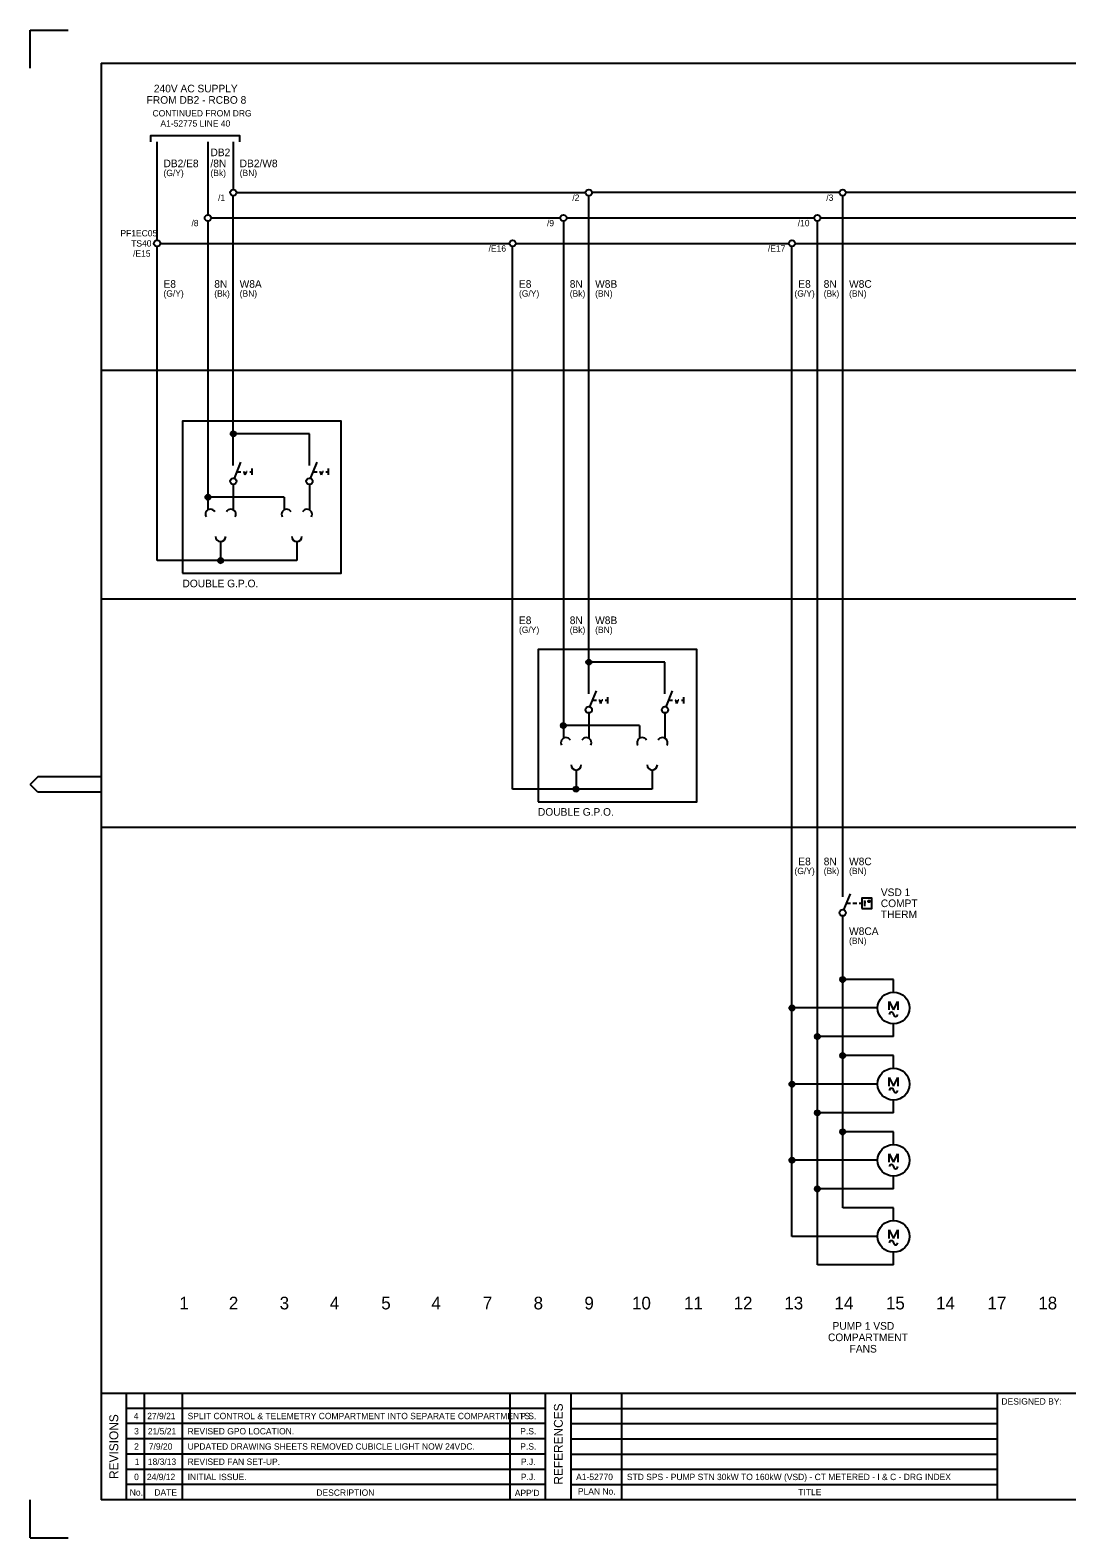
# Model space of a CAD drawing. Extents: x 0 to 841, y 0 to 594.
# Drawn here: x 0 to 408, y 0 to 594 of the extents above; entities that cross this region are included whole.
import ezdxf

# ---------------------------------------------------------------- set-up
doc = ezdxf.new("R2010")
doc.units = 0
for name, color, linetype in [('A1BORDER', 7, 'Continuous'), ('Level 1', 7, 'Continuous'), ('Level 10', 7, 'Continuous')]:
    doc.layers.add(name, color=color, linetype=linetype)

msp = doc.modelspace()

# ---------------------------------------------------------------- linework, layer by layer
at = {"layer": 'A1BORDER'}
for p, q in [((0, 594), (15, 594)), ((0, 579), (0, 594)), ((28, 581), (829, 581)), ((28, 581), (28, 15)), ((3, 299.76), (0, 296.76)), ((28, 299.76), (3, 299.76)), ((3, 293.76), (0, 296.76)), ((28, 293.76), (3, 293.76)), ((28, 57), (829, 57)), ((38, 15), (38, 57)), ((45, 15), (45, 57)), ((60, 15), (60, 57)), ((189, 15), (189, 57)), ((203, 15), (203, 57)), ((213, 15), (213, 57)), ((233, 15), (233, 57)), ((381, 15), (381, 57)), ((203, 51), (38, 51)), ((213, 51), (381, 51)), ((203, 45), (38, 45)), ((213, 45), (381, 45)), ((203, 39), (38, 39)), ((213, 39), (381, 39)), ((203, 33), (38, 33)), ((213, 33), (381, 33)), ((38, 27), (203, 27)), ((213, 27), (381, 27)), ((203, 21), (38, 21)), ((213, 21), (381, 21)), ((0, 0), (0, 15)), ((829, 15), (28, 15)), ((0, 0), (15, 0))]:
    msp.add_line(p, q, dxfattribs=at)
at = {"layer": 'Level 1'}
for p, q in [((50, 511.25), (50, 550)), ((70, 550), (70, 521.25)), ((80, 550), (80, 531.25)), ((79.98, 425), (79.98, 528.75)), ((81.25, 530), (218.75, 530)), ((219.98, 335), (219.98, 528.75)), ((318.75, 530), (221.25, 530)), ((320, 255), (320, 528.75)), ((438.75, 530), (321.25, 530)), ((70, 518.75), (70, 405)), ((71.25, 520), (208.75, 520)), ((210, 518.75), (210, 315)), ((211.25, 520), (308.75, 520)), ((310, 107.5), (310, 518.75)), ((311.25, 520), (428.75, 520)), ((50, 385), (50, 508.75)), ((51.25, 510), (188.75, 510)), ((190, 295), (190, 508.75)), ((191.25, 510), (298.75, 510)), ((300, 118.75), (300, 508.75)), ((301.25, 510), (418.75, 510)), ((28, 460), (829, 460)), ((109.98, 435), (79.98, 435)), ((109.98, 425), (109.98, 435)), ((79.98, 422.5), (79.98, 425)), ((79.98, 425), (79.98, 425)), ((80.44, 417.41), (82.98, 423.75)), ((109.98, 422.5), (109.98, 425)), ((109.98, 425), (109.98, 425)), ((110.44, 417.41), (112.98, 423.75)), ((81.48, 420), (82.98, 420)), ((83.98, 420), (84.31, 420)), ((84.73, 418.75), (84.31, 420)), ((84.73, 418.75), (85.15, 420)), ((85.48, 420), (85.15, 420)), ((86.48, 420), (87.48, 420)), ((87.48, 418.75), (87.48, 421.25)), ((111.48, 420), (112.98, 420)), ((113.98, 420), (114.31, 420)), ((114.73, 418.75), (114.31, 420)), ((114.73, 418.75), (115.15, 420)), ((115.48, 420), (115.15, 420)), ((116.48, 420), (117.48, 420)), ((117.48, 418.75), (117.48, 421.25)), ((70, 410), (70, 405)), ((100, 410), (70, 410)), ((79.98, 415), (79.98, 415)), ((79.98, 415), (79.98, 405)), ((100, 410), (100, 405)), ((109.98, 415), (109.98, 415)), ((109.98, 415), (109.98, 405)), ((75, 392.5), (75, 385)), ((105, 392.5), (105, 385)), ((105, 385), (50, 385)), ((28, 370), (829, 370)), ((249.98, 345), (219.98, 345)), ((249.98, 335), (249.98, 345)), ((219.98, 332.5), (219.98, 335)), ((219.98, 335), (219.98, 335)), ((220.44, 327.41), (222.98, 333.75)), ((249.98, 332.5), (249.98, 335)), ((249.98, 335), (249.98, 335)), ((250.44, 327.41), (252.98, 333.75)), ((221.48, 330), (222.98, 330)), ((223.98, 330), (224.31, 330)), ((224.73, 328.75), (224.31, 330)), ((224.73, 328.75), (225.15, 330)), ((225.48, 330), (225.15, 330)), ((226.48, 330), (227.48, 330)), ((227.48, 328.75), (227.48, 331.25)), ((251.48, 330), (252.98, 330)), ((253.98, 330), (254.31, 330)), ((254.73, 328.75), (254.31, 330)), ((254.73, 328.75), (255.15, 330)), ((255.48, 330), (255.15, 330)), ((256.48, 330), (257.48, 330)), ((257.48, 328.75), (257.48, 331.25)), ((219.98, 325), (219.98, 325)), ((219.98, 325), (219.98, 315)), ((249.98, 325), (249.98, 325)), ((249.98, 325), (249.98, 315)), ((210, 320), (210, 315)), ((240, 320), (210, 320)), ((240, 320), (240, 315)), ((215, 302.5), (215, 295)), ((245, 302.5), (245, 295)), ((245, 295), (190, 295)), ((28, 280), (829, 280)), ((320, 252.5), (320, 255)), ((320.46, 247.41), (323, 253.75)), ((321.5, 250), (323, 250)), ((324, 250), (325.5, 250)), ((326.5, 250), (327.5, 250)), ((320, 130), (320, 245)), ((340, 220), (320, 220)), ((340, 215), (340, 220)), ((333.75, 208.75), (300, 208.75)), ((340, 197.5), (340, 202.5)), ((340, 197.5), (310, 197.5)), ((340, 190), (320, 190)), ((340, 185), (340, 190)), ((333.75, 178.75), (300, 178.75)), ((340, 167.5), (340, 172.5)), ((340, 167.5), (310, 167.5)), ((340, 160), (320, 160)), ((340, 155), (340, 160)), ((333.75, 148.75), (300, 148.75)), ((340, 137.5), (310, 137.5)), ((340, 137.5), (340, 142.5)), ((340, 130), (320, 130)), ((340, 125), (340, 130)), ((333.75, 118.75), (300, 118.75)), ((340, 107.5), (310, 107.5)), ((340, 107.5), (340, 112.5))]:
    msp.add_line(p, q, dxfattribs=at)
for points in [[(47.5, 550), (47.5, 552.5), (82.5, 552.5), (82.5, 550)], [(328.38, 250.38), (329.13, 250.38)], [(328.63, 251.13), (328.63, 248.87)], [(330.36, 250.38), (330.18, 250.42), (330.05, 250.56), (329.99, 250.76), (330.05, 250.94), (330.18, 251.07), (330.36, 251.13), (330.56, 251.07), (330.7, 250.94), (330.74, 250.76), (330.7, 250.56), (330.56, 250.42), (330.36, 250.38)]]:
    msp.add_lwpolyline(points, dxfattribs=at)
for points in [[(60, 380), (122.5, 380), (122.5, 440), (60, 440)], [(200, 290), (262.5, 290), (262.5, 350), (200, 350)], [(327.5, 248), (331.5, 248), (331.5, 252), (327.5, 252)]]:
    msp.add_lwpolyline(points, close=True, dxfattribs=at)
for centre in [(80, 530), (220, 530), (320, 530), (70, 520), (210, 520), (310, 520), (50, 510), (190, 510), (300, 510), (79.98, 416.25), (109.98, 416.25), (219.98, 326.25), (249.98, 326.25), (320, 246.25)]:
    msp.add_circle(centre, 1.25, dxfattribs=at)
at = {"layer": 'Level 10'}
for p, q in [((79, 434.89), (80.6, 435.81)), ((79.04, 435.25), (80.26, 435.96)), ((79.09, 434.59), (80.81, 435.58)), ((79.25, 434.34), (80.95, 435.32)), ((79.5, 435.87), (79.5, 435.87)), ((79.5, 434.13), (81, 435)), ((79.88, 434.01), (80.92, 434.61)), ((69, 409.89), (70.6, 410.81)), ((69.04, 410.25), (70.26, 410.96)), ((69.09, 409.59), (70.81, 410.58)), ((69.25, 409.34), (70.95, 410.32)), ((69.5, 410.87), (69.5, 410.87)), ((69.5, 409.13), (71, 410)), ((69.88, 409.01), (70.92, 409.61)), ((74, 384.89), (75.6, 385.81)), ((74.04, 385.25), (75.26, 385.96)), ((74.09, 384.59), (75.81, 385.58)), ((74.25, 384.34), (75.95, 385.32)), ((74.5, 385.87), (74.5, 385.87)), ((74.5, 384.13), (76, 385)), ((74.88, 384.01), (75.92, 384.61)), ((219, 344.89), (220.6, 345.81)), ((219.04, 345.25), (220.26, 345.96)), ((219.09, 344.59), (220.81, 345.58)), ((219.25, 344.34), (220.95, 345.32)), ((219.5, 345.87), (219.5, 345.87)), ((219.5, 344.13), (221, 345)), ((219.88, 344.01), (220.92, 344.61)), ((209, 319.89), (210.6, 320.81)), ((209.04, 320.25), (210.26, 320.96)), ((209.5, 320.87), (209.5, 320.87)), ((209.09, 319.59), (210.81, 320.58)), ((209.25, 319.34), (210.95, 320.32)), ((209.5, 319.13), (211, 320)), ((209.88, 319.01), (210.92, 319.61)), ((214, 294.89), (215.6, 295.81)), ((214.04, 295.25), (215.26, 295.96)), ((214.09, 294.59), (215.81, 295.58)), ((214.25, 294.34), (215.95, 295.32)), ((214.5, 295.87), (214.5, 295.87)), ((214.5, 294.13), (216, 295)), ((214.88, 294.01), (215.92, 294.61)), ((319, 220), (320.99, 220)), ((319.05, 220.3), (320.95, 220.3)), ((319.2, 220.6), (320.8, 220.6)), ((319.56, 220.9), (320.44, 220.9)), ((320, 221), (320, 221)), ((319.05, 219.7), (320.95, 219.7)), ((319.2, 219.4), (320.8, 219.4)), ((319.56, 219.1), (320.44, 219.1)), ((299, 208.75), (300.99, 208.75)), ((299.05, 209.05), (300.95, 209.05)), ((299.05, 208.45), (300.95, 208.45)), ((299.2, 209.35), (300.8, 209.35)), ((299.2, 208.15), (300.8, 208.15)), ((299.56, 209.65), (300.44, 209.65)), ((300, 209.75), (300, 209.75)), ((338.33, 211.33), (340, 208)), ((338.33, 208), (338.33, 211.33)), ((340, 208), (341.67, 211.33)), ((341.67, 211.33), (341.67, 208)), ((299.56, 207.85), (300.44, 207.85)), ((309, 197.5), (310.99, 197.5)), ((309.05, 197.8), (310.95, 197.8)), ((309.05, 197.2), (310.95, 197.2)), ((309.2, 198.1), (310.8, 198.1)), ((309.2, 196.9), (310.8, 196.9)), ((309.56, 198.4), (310.44, 198.4)), ((309.56, 196.6), (310.44, 196.6)), ((310, 198.5), (310, 198.5)), ((319.05, 190.3), (320.95, 190.3)), ((319.2, 190.6), (320.8, 190.6)), ((319.56, 190.9), (320.44, 190.9)), ((320, 191), (320, 191)), ((319, 190), (320.99, 190)), ((319.05, 189.7), (320.95, 189.7)), ((319.2, 189.4), (320.8, 189.4)), ((319.56, 189.1), (320.44, 189.1)), ((299, 178.75), (300.99, 178.75)), ((299.05, 179.05), (300.95, 179.05)), ((299.05, 178.45), (300.95, 178.45)), ((299.2, 179.35), (300.8, 179.35)), ((299.56, 179.65), (300.44, 179.65)), ((300, 179.75), (300, 179.75)), ((338.33, 181.33), (340, 178)), ((338.33, 178), (338.33, 181.33)), ((340, 178), (341.67, 181.33)), ((341.67, 181.33), (341.67, 178)), ((299.2, 178.15), (300.8, 178.15)), ((299.56, 177.85), (300.44, 177.85)), ((309, 167.5), (310.99, 167.5)), ((309.05, 167.8), (310.95, 167.8)), ((309.05, 167.2), (310.95, 167.2)), ((309.2, 168.1), (310.8, 168.1)), ((309.2, 166.9), (310.8, 166.9)), ((309.56, 168.4), (310.44, 168.4)), ((309.56, 166.6), (310.44, 166.6)), ((310, 168.5), (310, 168.5)), ((319.2, 160.6), (320.8, 160.6)), ((319.56, 160.9), (320.44, 160.9)), ((320, 161), (320, 161)), ((319, 160), (320.99, 160)), ((319.05, 160.3), (320.95, 160.3)), ((319.05, 159.7), (320.95, 159.7)), ((319.2, 159.4), (320.8, 159.4)), ((319.56, 159.1), (320.44, 159.1)), ((299, 148.75), (300.99, 148.75)), ((299.05, 149.05), (300.95, 149.05)), ((299.2, 149.35), (300.8, 149.35)), ((299.56, 149.65), (300.44, 149.65)), ((300, 149.75), (300, 149.75)), ((338.33, 151.33), (340, 148)), ((338.33, 148), (338.33, 151.33)), ((340, 148), (341.67, 151.33)), ((341.67, 151.33), (341.67, 148)), ((299.05, 148.45), (300.95, 148.45)), ((299.2, 148.15), (300.8, 148.15)), ((299.56, 147.85), (300.44, 147.85)), ((309, 137.5), (310.99, 137.5)), ((309.05, 137.8), (310.95, 137.8)), ((309.05, 137.2), (310.95, 137.2)), ((309.2, 138.1), (310.8, 138.1)), ((309.2, 136.9), (310.8, 136.9)), ((309.56, 138.4), (310.44, 138.4)), ((310, 138.5), (310, 138.5)), ((309.56, 136.6), (310.44, 136.6)), ((338.33, 121.33), (340, 118)), ((338.33, 118), (338.33, 121.33)), ((340, 118), (341.67, 121.33)), ((341.67, 121.33), (341.67, 118))]:
    msp.add_line(p, q, dxfattribs=at)
for centre, radius in [((80, 435), 1), ((70, 410), 1), ((75, 385), 1), ((220, 345), 1), ((210, 320), 1), ((215, 295), 1), ((320, 220), 1), ((340, 208.75), 6.25), ((300, 208.75), 1), ((310, 197.5), 1), ((320, 190), 1), ((340, 178.75), 6.25), ((300, 178.75), 1), ((310, 167.5), 1), ((320, 160), 1), ((340, 148.75), 6.25), ((300, 148.75), 1), ((310, 137.5), 1), ((340, 118.75), 6.25)]:
    msp.add_circle(centre, radius, dxfattribs=at)
for centre, radius, start, end in [((71, 403.26795), 2, 30, 210), ((79, 403.26795), 2, 330, 150), ((101, 403.26795), 2, 30, 210), ((109, 403.26795), 2, 330, 150), ((75, 394.5), 2, 180, 0), ((105, 394.5), 2, 180, 0), ((211, 313.26795), 2, 30, 210), ((219, 313.26795), 2, 330, 150), ((241, 313.26795), 2, 30, 210), ((249, 313.26795), 2, 330, 150), ((215, 304.5), 2, 180, 0), ((245, 304.5), 2, 180, 0), ((339.17, 206.25), 0.83, 0, 180), ((340.83, 206.25), 0.83, 180, 0), ((339.17, 176.25), 0.83, 0, 180), ((340.83, 176.25), 0.83, 180, 0), ((339.17, 146.25), 0.83, 0, 180), ((340.83, 146.25), 0.83, 180, 0), ((339.17, 116.25), 0.83, 0, 180), ((340.83, 116.25), 0.83, 180, 0)]:
    msp.add_arc(centre, radius, start, end, dxfattribs=at)

# ---------------------------------------------------------------- texts
at = {"layer": 'A1BORDER'}
for s, height, p in [('DESIGNED BY:', 2.5, (382.5, 52.5)), ('No.', 2.50002, (39.21, 16.65)), ('DATE', 2.50002, (48.92, 16.65)), ('DESCRIPTION', 2.50002, (112.71, 16.57)), ("APP'D", 2.50002, (190.85, 16.44)), ('PLAN No.', 2.50002, (215.69, 17.06)), ('TITLE', 2.50002, (302.5, 16.81))]:
    msp.add_text(s, height=height, dxfattribs=at).set_placement(p)
for s, p in [('REVISIONS', (34.68, 23.2)), ('REFERENCES', (209.76, 20.96))]:
    msp.add_text(s, height=3.49998, rotation=90, dxfattribs=at).set_placement(p)
at = {"layer": 'Level 1'}
for s, height, p in [('240V AC SUPPLY', 3, (48.71387, 569.5)), ('FROM DB2 - RCBO 8', 3, (45.875, 565)), ('CONTINUED FROM DRG', 2.50002, (48.19078, 560.00002)), ('A1-52775 LINE 40', 2.50002, (51.3036, 556)), ('DB2', 3, (71, 544.3418)), ('DB2/E8', 3, (52.5, 540)), ('/8N', 3, (71, 540)), ('DB2/W8', 3, (82.5, 539.99999)), ('(G/Y)', 2.50002, (52.5, 536.49998)), ('(Bk)', 2.50002, (71, 536.49998)), ('(BN)', 2.50002, (82.5, 536.49998)), ('/1', 2.50002, (74.01631, 526.73908)), ('/2', 2.50002, (213.51826, 526.73908)), ('/3', 2.50002, (313.51826, 526.73908)), ('/8', 2.50002, (63.51826, 516.73908)), ('/9', 2.50002, (203.51826, 516.73908)), ('/10', 2.50002, (302.27313, 516.73908)), ('PF1EC05', 2.50002, (35.54945, 512.73911)), ('TS40', 2.50002, (39.78288, 508.73909)), ('/E15', 2.50002, (40.52995, 504.73907)), ('/E16', 2.50002, (180.52995, 506.73908)), ('/E17', 2.50002, (290.52995, 506.73908)), ('E8', 3, (52.5, 492.49999)), ('8N', 3, (72.5, 492.49999)), ('W8A', 3, (82.5, 492.49999)), ('E8', 3, (192.5, 492.49999)), ('8N', 3, (212.5, 492.49999)), ('W8B', 3, (222.5, 492.49999)), ('E8', 3, (302.5, 492.49999)), ('8N', 3, (312.5, 492.49999)), ('W8C', 3, (322.5, 492.49999)), ('(G/Y)', 2.50002, (52.5, 488.99997)), ('(Bk)', 2.50002, (72.5, 488.99997)), ('(BN)', 2.50002, (82.5, 488.99997)), ('(G/Y)', 2.50002, (192.5, 488.99997)), ('(Bk)', 2.50002, (212.5, 488.99997)), ('(BN)', 2.50002, (222.5, 488.99997)), ('(G/Y)', 2.50002, (301, 488.99997)), ('(Bk)', 2.50002, (312.5, 488.99997)), ('(BN)', 2.50002, (322.5, 488.99997)), ('DOUBLE G.P.O.', 3, (59.98, 374.49998)), ('E8', 3, (192.5, 360)), ('8N', 3, (212.5, 360)), ('W8B', 3, (222.5, 360)), ('(G/Y)', 2.50002, (192.5, 356.49998)), ('(Bk)', 2.50002, (212.5, 356.49998)), ('(BN)', 2.50002, (222.5, 356.49998)), ('DOUBLE G.P.O.', 3, (199.98, 284.49998)), ('E8', 3, (302.5, 265)), ('8N', 3, (312.5, 265)), ('W8C', 3, (322.5, 265)), ('(G/Y)', 2.50002, (301, 261.49998)), ('(Bk)', 2.50002, (312.5, 261.49998)), ('(BN)', 2.50002, (322.5, 261.49998)), ('VSD 1', 3, (335, 252.8418)), ('COMPT', 3, (335, 248.5)), ('THERM', 3, (335, 244.1582)), ('W8CA', 3, (322.5, 237.5)), ('(BN)', 2.50002, (322.5, 233.99998)), ('(BN)', 2.50002, (322.5, 233.99998)), ('2', 4.99998, (78.26, 90)), ('3', 4.99998, (98.26, 90)), ('8', 4.99998, (198.26, 90)), ('9', 4.99998, (218.26, 90)), ('10', 4.99998, (237.01, 90)), ('12', 4.99998, (277.01, 90)), ('13', 4.99998, (297.01, 90)), ('18', 4.99998, (397.01, 90)), ('1', 4.99998, (58.76, 90)), ('4', 4.99998, (118.01, 90)), ('5', 4.99998, (138.26, 90)), ('4', 4.99998, (158.01098, 90)), ('7', 4.99998, (178.26, 90)), ('11', 4.99998, (257.51, 90)), ('14', 4.99998, (316.76, 90)), ('15', 4.99998, (337.01, 90)), ('14', 4.99998, (356.76098, 90)), ('17', 4.99998, (377.01, 90)), ('PUMP 1 VSD', 3, (315.99512, 82)), ('COMPARTMENT', 3, (314.20215, 77.5)), ('FANS', 3, (322.71875, 73)), ('4', 2.50002, (40.81549, 46.75)), ('27/9/21', 2.50002, (46.09354, 46.75)), ('SPLIT CONTROL & TELEMETRY COMPARTMENT INTO SEPARATE COMPARTMENTS.', 2.50002, (62, 46.75)), ('P.S.', 2.50002, (193.01549, 46.75)), ('3', 2.50002, (40.94, 40.75)), ('21/5/21', 2.50002, (46.34256, 40.75)), ('REVISED GPO LOCATION.', 2.50002, (62, 40.75)), ('P.S.', 2.50002, (193.01549, 40.75)), ('2', 2.50002, (40.94, 34.75)), ('7/9/20', 2.50002, (46.7161, 34.75)), ('UPDATED DRAWING SHEETS REMOVED CUBICLE LIGHT NOW 24VDC.', 2.50002, (62, 34.75)), ('P.S.', 2.50002, (193.01549, 34.75)), ('1', 2.50002, (41.18903, 28.75)), ('18/3/13', 2.50002, (46.34256, 28.75)), ('REVISED FAN SET-UP.', 2.50002, (62, 28.75)), ('P.J.', 2.50002, (193.26451, 28.75)), ('0', 2.50002, (40.94, 22.75)), ('24/9/12', 2.50002, (45.96903, 22.75)), ('INITIAL ISSUE.', 2.50002, (62, 22.75)), ('P.J.', 2.50002, (193.26451, 22.75)), ('A1-52770', 2.50002, (215, 22.75)), ('STD SPS - PUMP STN 30kW TO 160kW (VSD) - CT METERED - I & C - DRG INDEX', 2.50002, (235, 22.75))]:
    msp.add_text(s, height=height, dxfattribs=at).set_placement(p)

doc.saveas('drawing.dxf')
